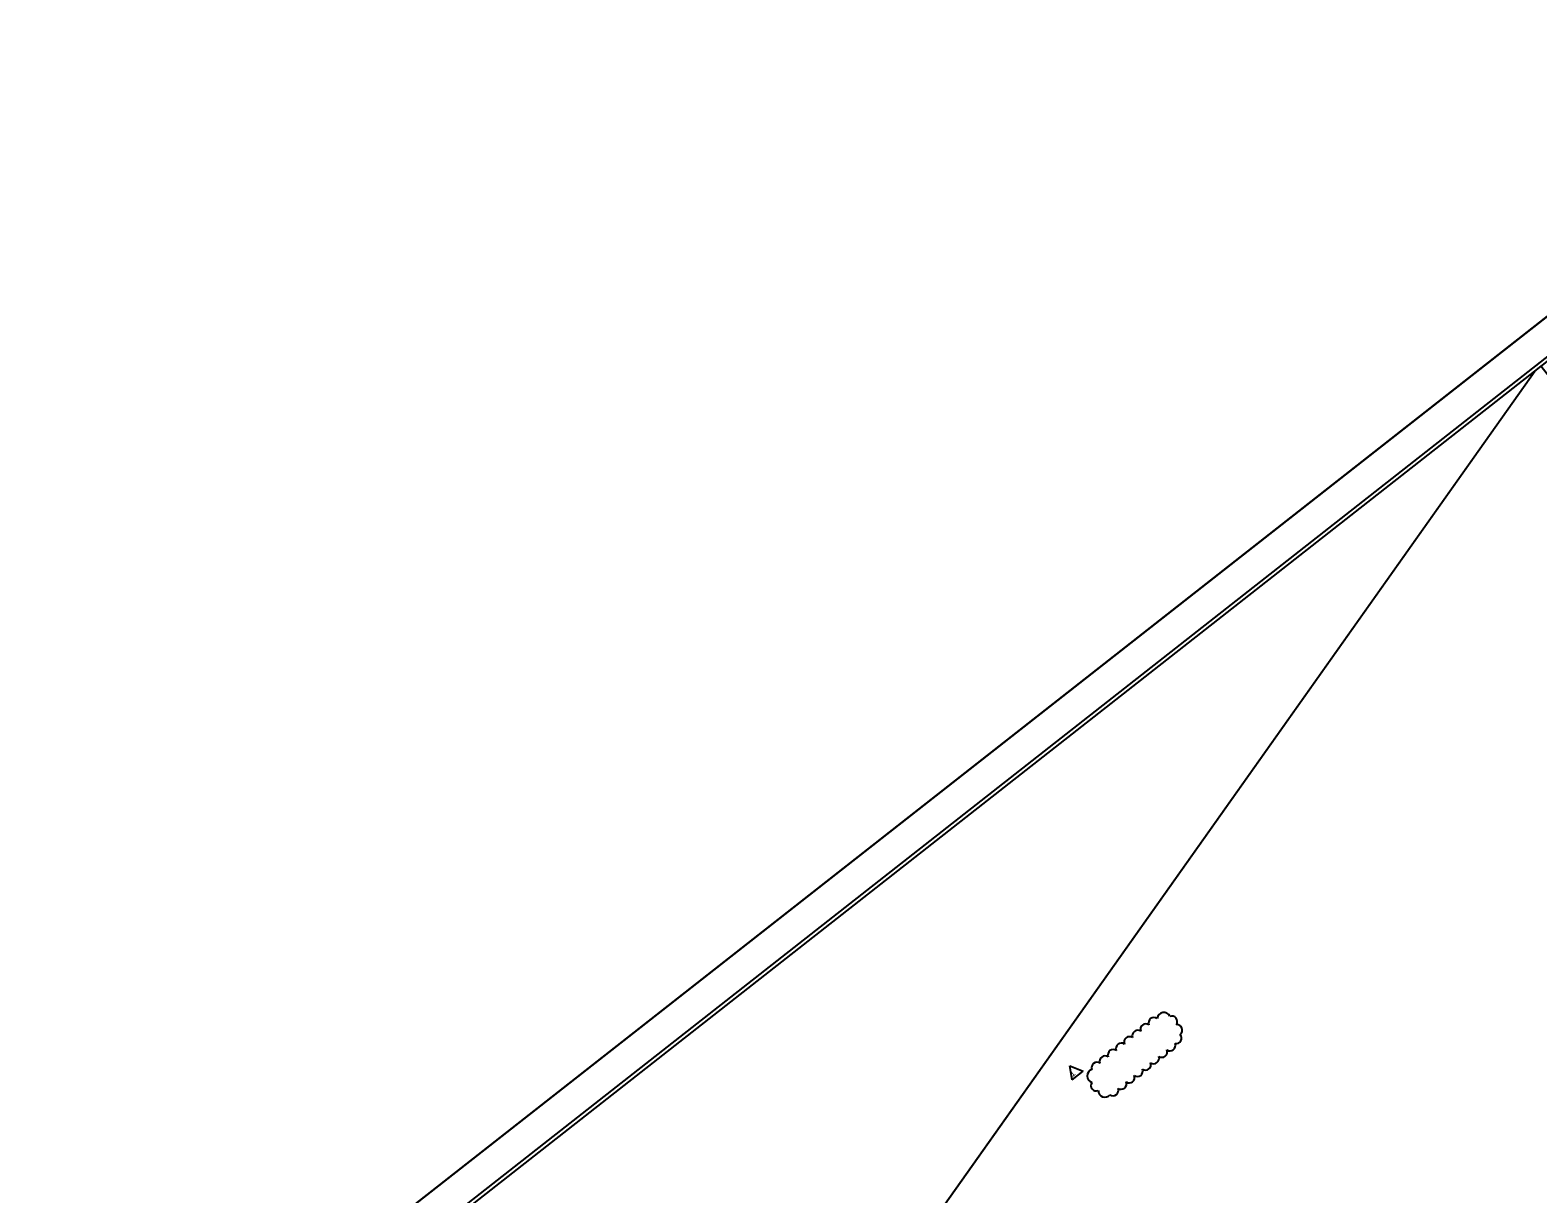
# Model space of a CAD drawing. Extents: x 2176242 to 2178501, y 76147 to 78096.
# Drawn here: x 2176242 to 2177304, y 77232 to 78051 of the extents above; entities that cross this region are included whole.
import ezdxf

# ---------------------------------------------------------------- set-up
doc = ezdxf.new("R2010")
doc.units = 0
for name, color, linetype in [('CTL Primary Horizontal and Vertical CELL', 7, 'Continuous'), ('CTL Primary Horizontal CELL', 7, 'Continuous'), ('CTL Primary Horizontal Cogo Elevation', 7, 'Continuous'), ('CTL Primary Horizontal Cogo Number', 7, 'Continuous'), ('Exist Other Culture Sign Cogo Point CELL', 7, 'Continuous'), ('Exist Structure Minor Pipes RCP 18 Inch', 7, 'Continuous'), ('Exist Utilities Other Traffic Signal Box CELL', 7, 'Continuous')]:
    doc.layers.add(name, color=color, linetype=linetype)

msp = doc.modelspace()

# ---------------------------------------------------------------- linework, layer by layer
at = {"layer": 'CTL Primary Horizontal and Vertical CELL'}
msp.add_lwpolyline([(2176602.4, 76823.6), (2177302, 77811.1), (2177302, 77811.1), (2177306.5, 77814.6), (2177363.5, 77741.9), (2177469.3, 77824.8), (2177519.3, 77761), (2177676.8, 77884.4), (2178217.5, 77194.6), (2177036.9, 76269.2)], close=True, dxfattribs=at)
at = {"layer": 'CTL Primary Horizontal CELL'}
msp.add_lwpolyline([(2177578, 78030.7), (2176266.4, 77002.6), (2176917.3, 76172.2), (2178228.9, 77200.3)], close=True, dxfattribs=at)
at = {"layer": 'CTL Primary Horizontal Cogo Elevation'}
msp.add_line((2177567.7, 78051.1), (2176242.3, 77012.2), dxfattribs=at)
at = {"layer": 'CTL Primary Horizontal Cogo Number'}
msp.add_lwpolyline([(2177567.7, 78051.1), (2176242.3, 77012.2), (2176920.9, 76146.5), (2178246.3, 77185.4)], close=True, dxfattribs=at)
at = {"layer": 'Exist Other Culture Sign Cogo Point CELL'}
msp.add_lwpolyline([(2177569.7, 78021), (2176389.2, 77095.6), (2177036.9, 76269.2), (2178217.5, 77194.6)], close=True, dxfattribs=at)
at = {"layer": 'Exist Structure Minor Pipes RCP 18 Inch'}
for p, q in [((2176974.6, 77322.1), (2176984, 77318.2)), ((2176976.2, 77312.1), (2176974.6, 77322.1)), ((2176976.2, 77312.1), (2176984, 77318.2))]:
    msp.add_line(p, q, dxfattribs=at)
for centre, radius, start, end in [((2177028.1, 77347.7), 3.82, 55.591, 200.591), ((2177033.8, 77352.2), 3.82, 55.591, 200.591), ((2177040.8, 77354.7), 4.8, 26.5514, 171.5514), ((2177046.4, 77353.2), 3.82, 325.591, 110.591), ((2177049.8, 77347.1), 3.99, 308.5951, 93.5951), ((2177016.6, 77338.7), 3.82, 55.591, 200.591), ((2177022.4, 77343.2), 3.82, 55.591, 200.591), ((2177049.5, 77341.4), 3.82, 257.9849, 42.9849), ((2176999.4, 77325.2), 3.82, 55.591, 200.591), ((2177005.2, 77329.7), 3.82, 55.591, 200.591), ((2177010.9, 77334.2), 3.82, 55.591, 200.591), ((2177039.4, 77331.8), 3.82, 235.591, 20.591), ((2177045.1, 77336.3), 3.82, 235.591, 20.591), ((2176991.6, 77314.8), 4.79, 107.8133, 252.8133), ((2176993.7, 77320.7), 3.82, 55.591, 200.591), ((2177022.2, 77318.3), 3.82, 235.591, 20.591), ((2177027.9, 77322.8), 3.82, 235.591, 20.591), ((2177033.6, 77327.3), 3.82, 235.591, 20.591), ((2176993.3, 77308.1), 3.82, 145.591, 290.591), ((2177010.7, 77309.3), 3.82, 235.591, 20.591), ((2177016.4, 77313.8), 3.82, 235.591, 20.591), ((2176999.2, 77304.4), 4.53, 177.9857, 322.9857), ((2177005, 77304.8), 3.82, 235.591, 20.591)]:
    msp.add_arc(centre, radius, start, end, dxfattribs=at)
at = {"layer": 'Exist Utilities Other Traffic Signal Box CELL'}
msp.add_line((2176602.4, 76823.6), (2177302, 77811.1), dxfattribs=at)

# ---------------------------------------------------------------- texts
at = {"layer": 'Exist Structure Minor Pipes RCP 18 Inch'}
msp.add_text(' 1', height=4.5, rotation=38.091, dxfattribs=at).set_placement((2176975, 77312.9))

doc.saveas('drawing.dxf')
